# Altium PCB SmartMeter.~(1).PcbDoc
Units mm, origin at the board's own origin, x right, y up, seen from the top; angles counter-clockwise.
Board outline 36.42 x 43 mm, 2 copper layers (Top Layer, Bottom Layer), stack 0.071 mm thick; 33 components, 27 nets, 131 pads, 18 vias.
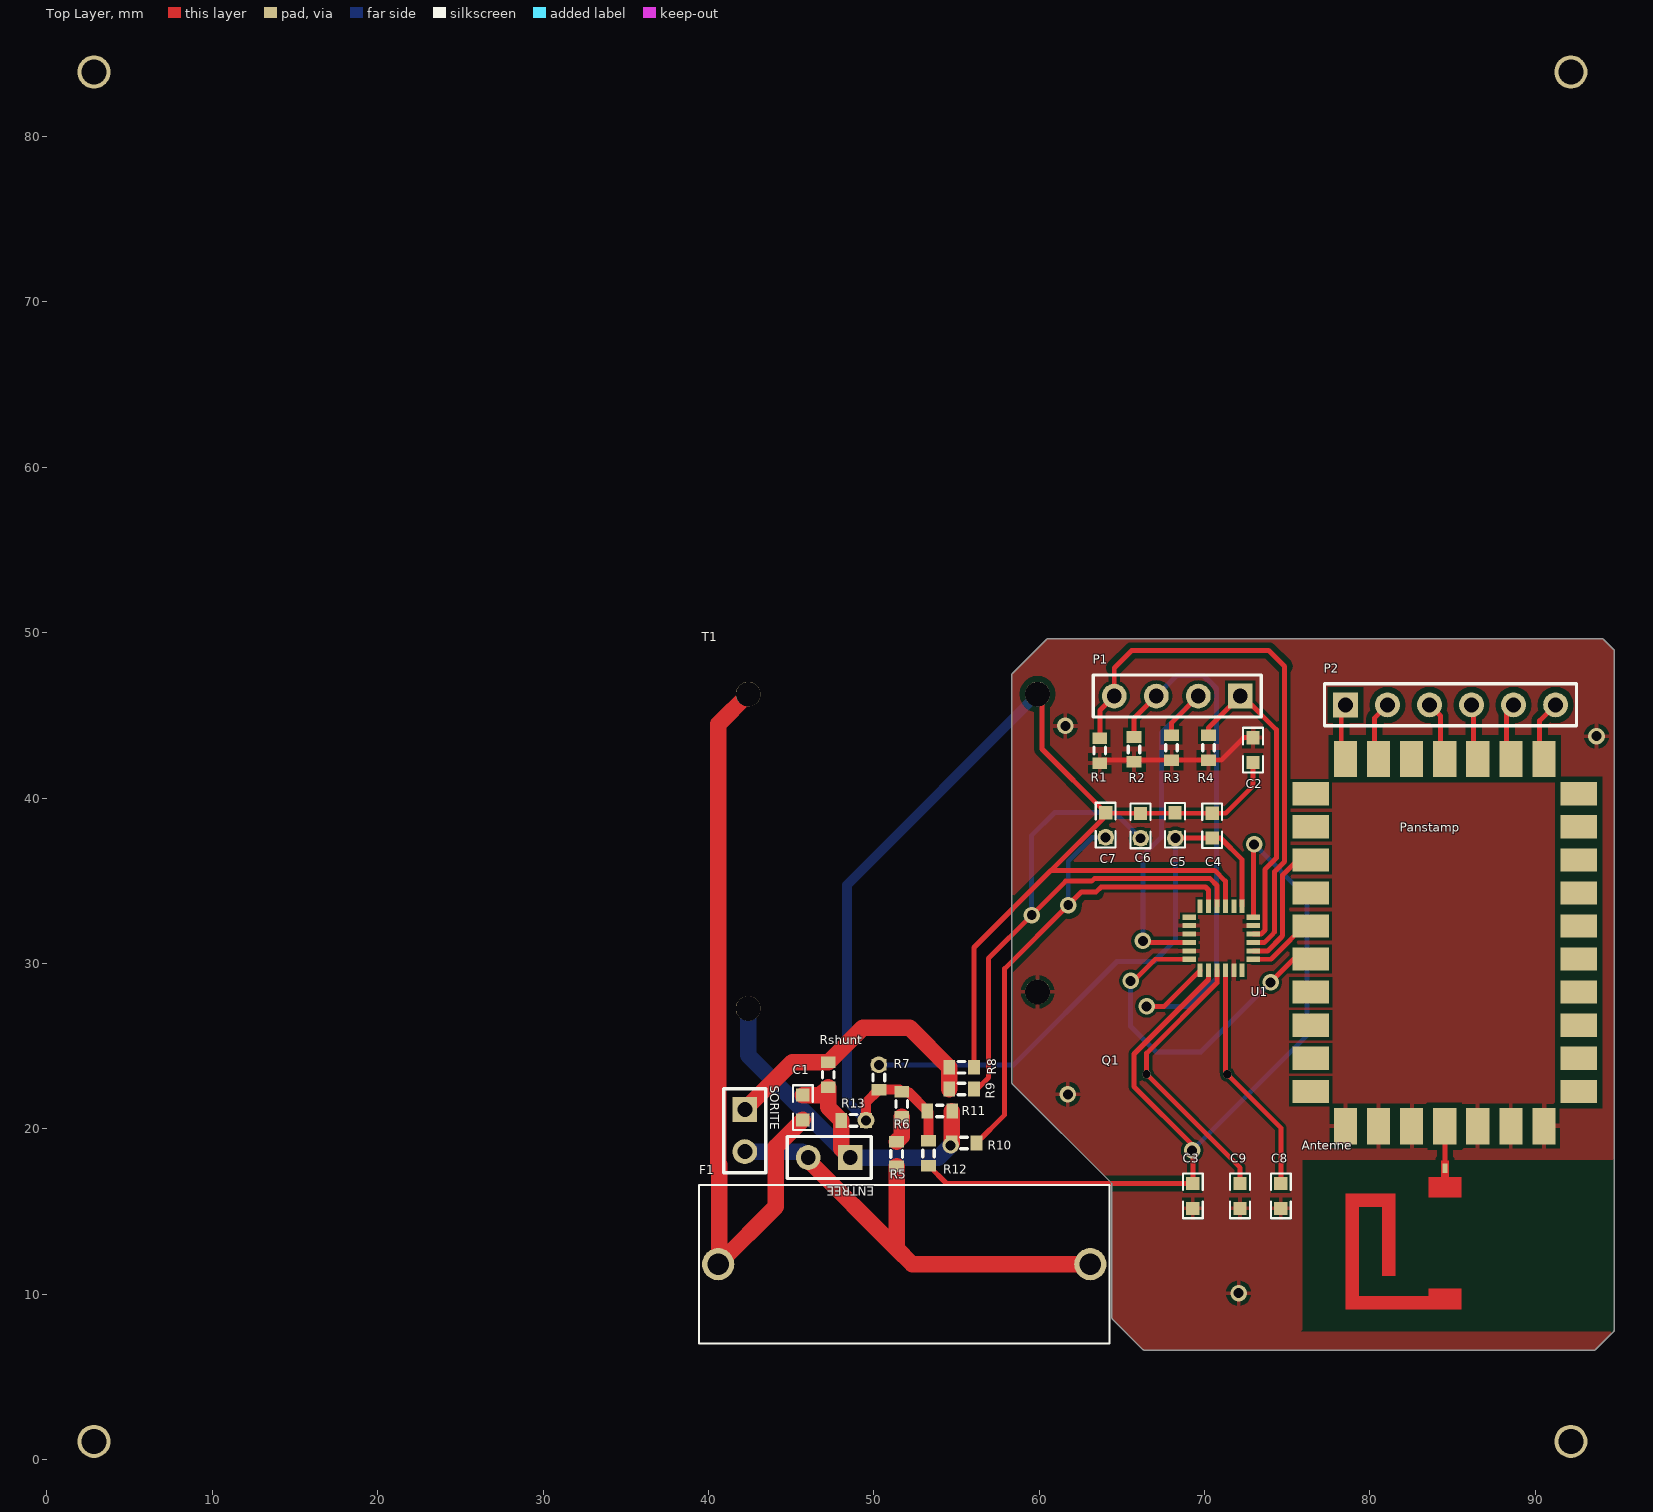
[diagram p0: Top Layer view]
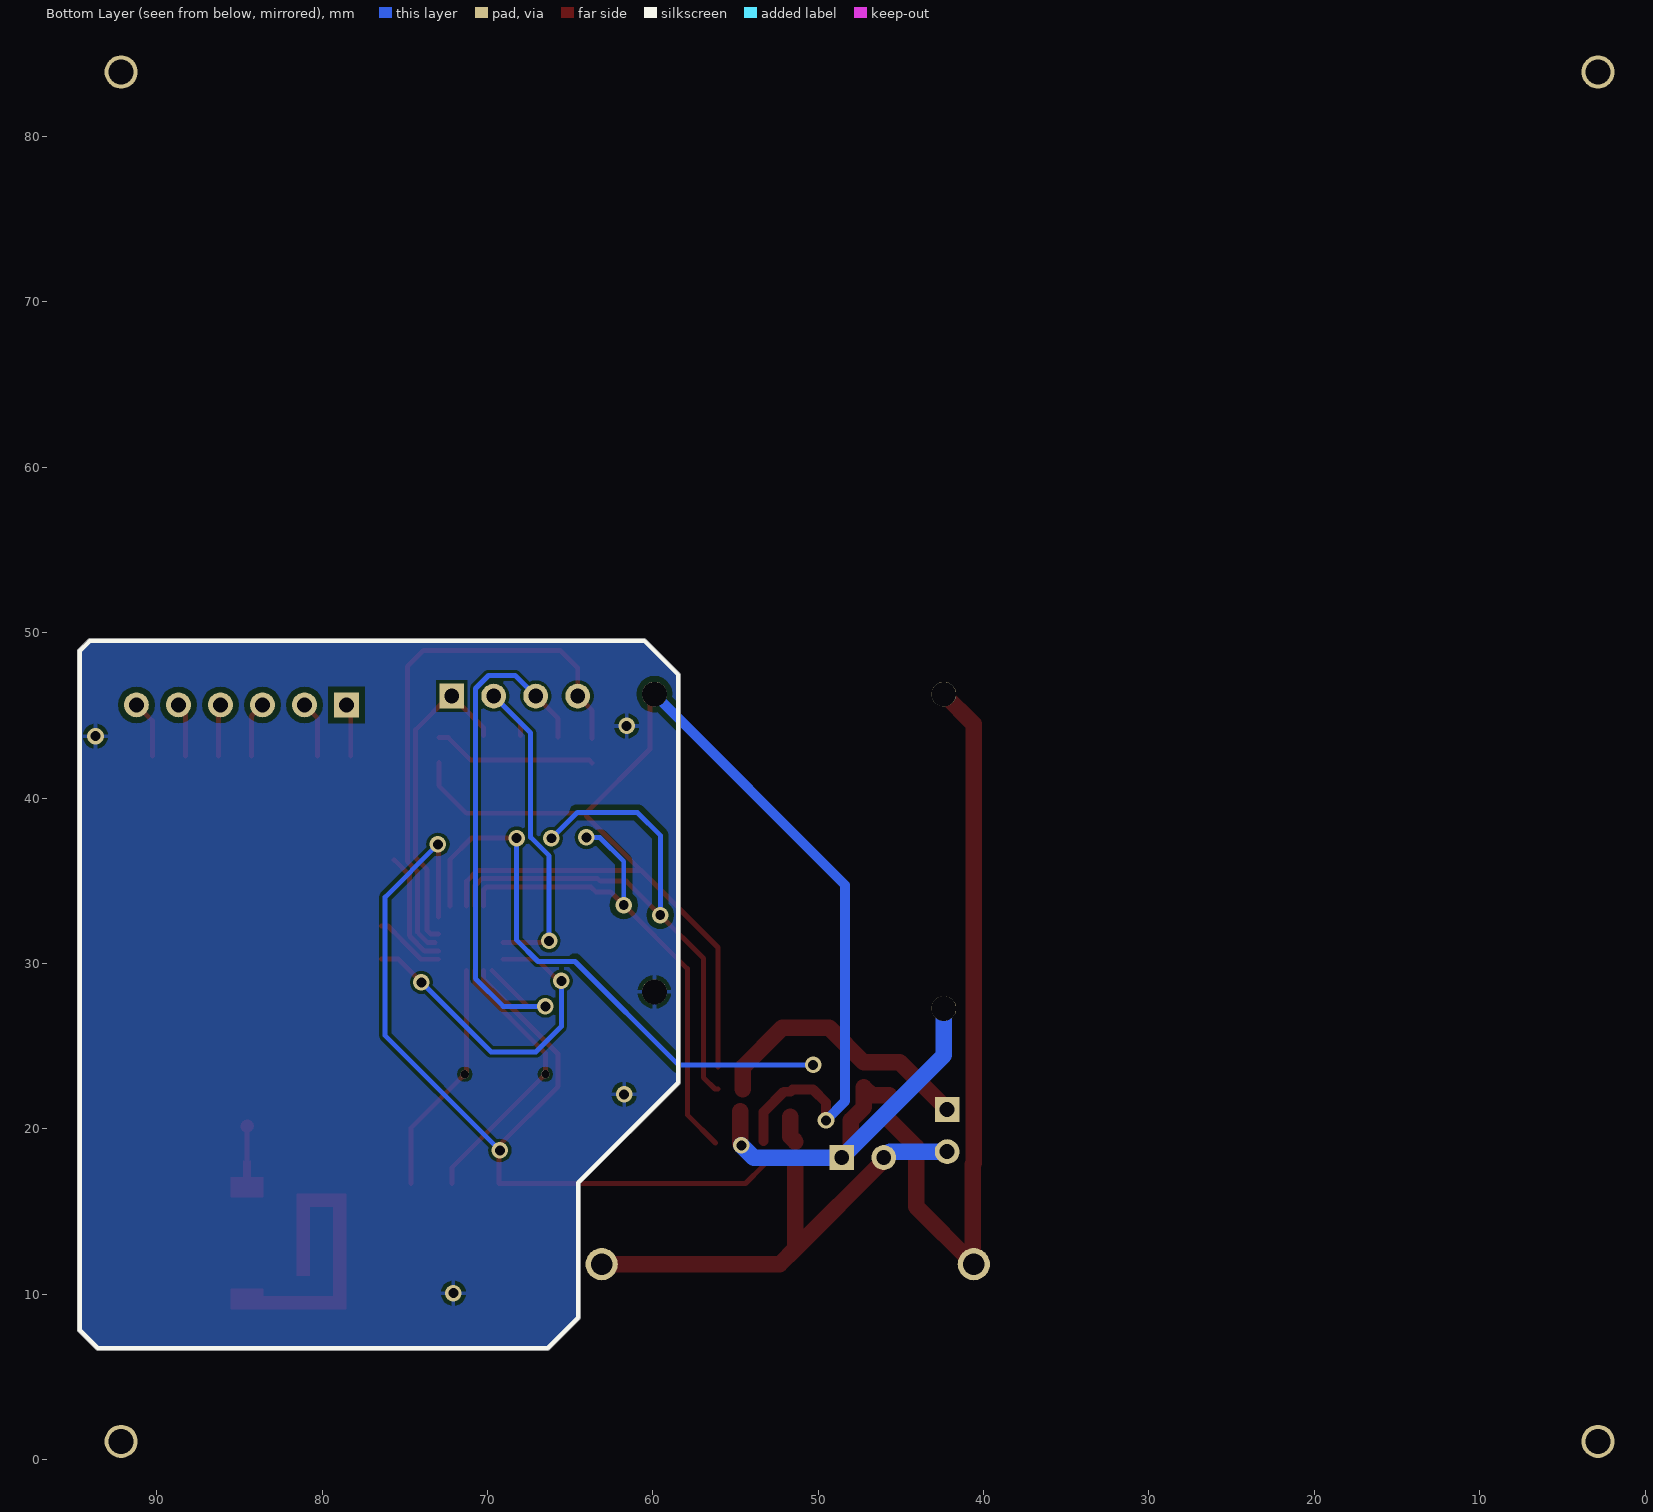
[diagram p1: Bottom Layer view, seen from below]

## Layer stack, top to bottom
Top Layer: signal copper 0.0356
Bottom Layer: signal copper 0.0356

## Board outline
58.393,22.694 64.401,16.686 64.401,8.572 ccw(c64.529,8.572) 64.439,8.482 66.267,6.654 ccw(c66.358,6.744) 66.358,6.616 93.561,6.616 ccw(c93.561,6.744) 93.651,6.654 94.743,7.746 94.743,7.745 ccw(c94.653,7.836) 94.78,7.836 94.78,48.882 ccw(c94.653,48.882) 94.743,48.973 94.743,48.972 94.134,49.582 ccw(c94.043,49.492) 94.043,49.619 60.515,49.619 ccw(c60.515,49.492) 60.425,49.582 58.393,47.55 58.394,47.55 ccw(c58.483,47.46) 58.356,47.46 58.356,22.784 ccw(c58.483,22.784)

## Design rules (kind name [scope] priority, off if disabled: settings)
Clearance Clearance_Max [InComponent('U1')] p1: gap=0.15
Clearance Clearance_INU [WithinRoom('INU')] p2: gap=0.2
Clearance [All] p3: gap=0.35
PolygonConnect [All] p1: connectstyle=Relief reliefconductorwidth=0.254 reliefentries=4 polygonreliefangle="90 Angle" airgapwidth=0.254
RoomDefinition INU [not IsComponent] p1: confinementstyle=ConfineIn formatcopy=TRUE lockcomponents=FALSE outline 63.055,13.373 76.772,13.373 76.772,48.476 63.055,48.476
RoutingVias [All] p1: holewidth=0.711 width=1.27 viastyle="Through Hole" minholewidth=0.711 minwidth=1.27 maxholewidth=0.711 maxwidth=1.27
SolderMaskExpansion [All] p1: expansion=0.102
UnpouredPolygon [All] p1: allowunpoured=FALSE
Width Width_INU [WithinRoom('INU')] p1: maxlimit=0.8 minlimit=0.2 preferedwidth=0.3 toplayer_maxwidth=0.4 minimp=50.000000 maximp=50.000000 favimp=50.000000
Width Width_HT [InNetClass('HT')] p2: maxlimit=3 minlimit=1 preferedwidth=2.184 minimp=50.000000 maximp=50.000000 favimp=50.000000
Width [All] p3: maxlimit=0.8 minlimit=0.3 preferedwidth=0.6 minimp=50.000000 maximp=50.000000 favimp=50.000000
29 further rules are at their usual default settings.

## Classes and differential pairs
net class HT: NetC1_1 NetC1_2 NetF1_1 NetR5_2 "NEUTRAL OUT"
component class "Components Class 1": U1
component class SmartMeter: C1 C2 C3 C4 C5 C6 C7 C8 C9 F1 P1 P2 Panstamp Q1 R1 R2 R3 R4 R5 R6 R7 R8 R9 R10 R11 R12 R13 Rshunt T1

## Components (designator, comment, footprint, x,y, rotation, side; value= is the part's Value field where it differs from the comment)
Antenne "Comment" PCBComponent_1#1 84.785,18.085 r180 top
C1 "100pF" "WCAP-CSGP 0603, H=0.8mm" 45.707,21.285 r90 top
C2 "100pF" "WCAP-CSGP 0603, H=0.8mm" 72.936,42.901 r90 top
C3 "100pF" "WCAP-CSGP 0603, H=0.8mm" 69.291,15.938 r270 top
C4 "1000pF" "WCAP-CSGP 0603, H=0.8mm" 70.46,38.329 r270 top
C5 "100pF" "WCAP-CSGP 0603, H=0.8mm" 68.212,38.354 r270 top
C6 "1uF" "WCAP-CSGP 0603, H=0.8mm" 66.129,38.316 r90 top
C7 "1uF" "WCAP-CSGP 0603, H=0.8mm" 64.021,38.367 r270 top
C8 "18pF" "WCAP-CSGP 0603, H=0.8mm" 74.612,15.938 r270 top
C9 "18pF" "WCAP-CSGP 0603, H=0.8mm" 72.149,15.938 r270 top
ENTREE "Comment" HDR1X2 48.578,18.263 r180 top
F1 "696103201002" 696103201002 51.841,11.811 r180 top
P1 "Header 4" HDR1X4 72.161,46.164 r180 top
P2 "Header 6" HDR1X6 78.524,45.631 r0 top
Panstamp "Panstamp" PCBComponent_1#2 92.621,22.263 r180 top
Q1 "Comment" PCBComponent_1#3 71.374,23.292 r180 top
R1 "Res3" J1-0603 63.665,42.862 r270 top
R2 "Res3" J1-0603 65.735,42.939 r270 top
R3 "Res3" J1-0603 68.008,43.04 r270 top
R4 "Res3" J1-0603 70.244,43.04 r270 top
R5 "Res3" J1-0603 51.384,18.479 r90 top
R6 "Res3" J1-0603 51.689,21.488 r90 top
R7 "Res3" J1-0603 50.305,23.114 r270 top
R8 "Res3" J1-0603 55.308,23.724 r0 top
R9 "Res3" J1-0603 55.308,22.403 r180 top
R10 "Res3" J1-0603 55.461,19.139 r180 top
R11 "Res3" J1-0603 53.988,21.082 r0 top
R12 "Res3" J1-0603 53.315,18.517 r90 top
R13 "Res3" J1-0603 48.781,20.511 r180 top
Rshunt "Res3" J1-0603 47.244,23.266 r90 top
SORITE "Comment" HDR1X2 42.202,21.158 r270 top
T1 "Alimentation 230AC/3.3DC" PCBComponent_1#4 42.405,46.279 r0 top
U1 "Maxim_78M6610+LMU" 21_0139I_T2444_4 71.006,31.521 r0 top

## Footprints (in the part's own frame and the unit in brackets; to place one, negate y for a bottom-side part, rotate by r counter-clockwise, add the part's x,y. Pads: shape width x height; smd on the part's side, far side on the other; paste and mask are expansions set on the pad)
21_0139I_T2444_4 [mil]
  rect 32x12 smd: 1(-76.5,50) 2(-76.5,30) 3(-76.5,10) 4(-76.5,-10) 5(-76.5,-30) 6(-76.5,-50) 13(76.5,-50) 14(76.5,-30) 15(76.5,-10) 16(76.5,10) 17(76.5,30) 18(76.5,50)
  rect 12x32 smd: 7(-50,-76.5) 8(-30,-76.5) 9(-10,-76.5) 10(10,-76.5) 11(30,-76.5) 12(50,-76.5) 19(50,76.5) 20(30,76.5) 21(10,76.5) 22(-10,76.5) 23(-30,76.5) 24(-50,76.5)
696103201002 [mm] "PCB - Clip Cover - THR"
  round 1.95 hole 1.3: 1(-11.25,0) 2(11.25,0)
  silkscreen extent -12.4,-4.8 12.4,4.8, body extent -12.4,-4.8 12.4,4.8, height 25
HDR1X2 [mm] "Connector; Header; 2 Position"
  rect 1.5x1.5 hole 0.9: 1(0,0)
  round 1.5 hole 0.9: 2(2.54,0)
  silkscreen extent -1.27,-1.27 3.81,1.27
HDR1X4 [mm] "Connector; Header; 4 Position"
  rect 1.5x1.5 hole 0.9: 1(0,0)
  round 1.5 hole 0.9: 2(2.54,0) 3(5.08,0) 4(7.62,0)
  silkscreen extent -1.27,-1.27 8.89,1.27
HDR1X6 [mm] "Connector; Header; 6 Position"
  rect 1.5x1.5 hole 0.9: 1(0,0)
  round 1.5 hole 0.9: 2(2.54,0) 3(5.08,0) 4(7.62,0) 5(10.16,0) 6(12.7,0)
  silkscreen extent -1.27,-1.27 13.97,1.27
J1-0603 [mm] "Chip Resistor, Body 1.6x0.8mm, IPC High Density"
  rect 0.7x0.9 smd: 1(-0.75,0) 2(0.75,0)
  silkscreen extent -0.2,-0.35 0.2,0.35, body extent -0.85,-0.48 0.85,0.48, height 0.9
PCBComponent_1#1 [mm]
  rect 0.3x0.6 smd: 0(0.245,0.47)
  Top Layer region: 0,0 0.5,0 0.5,1 0,1
  Top Layer region: -0.75,1 1.25,1 1.25,2.25 -0.75,2.25
  Top Layer region: -0.75,7.75 1.25,7.75 1.25,9 -0.75,9
  Top Layer region: 1.25,8.2 6.25,8.2 6.25,9 1.25,9
  Top Layer region: 5.45,2 6.25,2 6.25,9 5.45,9
  Top Layer region: 3.25,2 5.45,2 5.45,2.8 3.25,2.8
  Top Layer region: 3.25,2 4.05,2 4.05,7 3.25,7
PCBComponent_1#2 [mm]
  rect 2.2x1.4 smd: 1(0,0) 2(0,-1.999) 3(0,-4) 4(0,-6) 5(0,-8) 6(0,-10) 7(0,-12) 8(0,-14) 9(0,-16) 10(0,-18) 18(16.2,-18) 19(16.2,-16) 20(16.2,-14) 21(16.2,-12) 22(16.2,-10) 23(16.2,-8) 24(16.2,-6) 25(16.2,-4) 26(16.2,-2) 27(16.2,0)
  rect 1.4x2.2 smd: 11(2.1,-20.1) 12(4.1,-20.1) 13(6.1,-20.1) 14(8.1,-20.1) 15(10.1,-20.1) 16(12.1,-20.1) 17(14.1,-20.1) 28(14.1,2.1) 29(12.1,2.1) 30(10.1,2.1) 31(8.1,2.1) 32(6.1,2.1) 33(4.1,2.1) 34(2.1,2.1)
PCBComponent_1#3 [mm]
  round 0.5 hole 0.5: 1(0,0) 2(4.877,0)
PCBComponent_1#4 [mm]
  round 1.5 hole 1.5: 1(17.5,-18) 2(17.5,0) 3(0,0) 4(0,-19)
"WCAP-CSGP 0603, H=0.8mm" [mm] "MLCC 0603, H=0.8mm"
  rect 0.8x0.8 smd: 1(-0.75,0) 2(0.75,0)
  silkscreen extent -1.35,-0.6 1.35,0.6, body extent -0.8,-0.4 0.8,0.4, height 0.77

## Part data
C1 C2 C3 C4 C5 C6 C7 C8 C9: library part 0603C-1UF-10V-X5R-TDK, "CAPACITOR 0603 CERAMIC"
ENTREE SORITE: library part "Header 2"
F1: library part "WR-FSH, 696103201002", "WR-FSH Fuseholder THR Blocks PCB Clip Cover"
P1: "Header, 4-Pin"
P2: "Header, 6-Pin"
Panstamp: "Panstamp NRG 2.0"
Q1: library part Component_1
R1 R2 R3 R4 R5 R6 R7 R8 R9 R10 R11 R12 R13 Rshunt: "Resistor"
U1: library part "Maxim78M6610 + LMU", "Mesure d'énergie IC ENERGY MM PROCESSOR 24TQFN"

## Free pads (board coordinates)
  round 2 hole 1.5: 1(2.85,83.9) 2(92.15,83.9) 3(92.15,1.1) 4(2.85,1.1)

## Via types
v1: diameter 1, hole 0.6, Top Layer to Bottom Layer, 18 vias

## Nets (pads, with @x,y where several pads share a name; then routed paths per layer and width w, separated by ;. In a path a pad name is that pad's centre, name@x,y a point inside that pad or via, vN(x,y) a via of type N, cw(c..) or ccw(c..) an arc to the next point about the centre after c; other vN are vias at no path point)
Antenne: Antenne.0 Panstamp.31 | length 2.6
  Top Layer w0.3: Antenne.0 Panstamp.31@84.54,20.144
  Top Layer w0.8: Panstamp.31 Panstamp.31@84.54,20.144
GND: C2.2 C3.2 C8.2 C9.2 Panstamp.28 Panstamp.29 Panstamp.30 Panstamp.32 Panstamp.33 Panstamp.34 R1.2 R2.2 R3.2 R4.2 T1.1 U1.2 U1.3 U1.5 U1.11 U1.17 | length 9.9
  Top Layer w0.3: R1.2 63.843,42.29 R3.2 R4.2 71.005,42.29 72.365,43.651 C2.2
  other v1: 72.06,10.058 61.735,22.085 93.701,43.739 61.582,44.361
NetC1_1: C1.1 F1.2 T1.3 | length 46
  Top Layer w1: F1.2 F1.2@40.653,11.872 ; T1.3 40.602,44.476 40.602,17.905 40.653,17.854 F1.2@40.653,11.872 ; C1.1 44.082,18.91 44.082,15.301 F1.2@40.653,11.872
NetC1_2: C1.2 ENTREE.1 R10.2 R11.2 R13.2 Rshunt.1 T1.4 | length 26.4
  Top Layer w1: C1.2 46.763,22.035 Rshunt.1 47.244,21.297 R13.2 48.031,18.809 ENTREE.1 ; R10.2 R11.2@54.711,21.061
  Bottom Layer w1: T1.4 42.405,24.435 ENTREE.1 53.911,18.263 v1(54.648,18.999)
NetC2_1: C2.1 C4.1 C5.1 C6.2 C7.1 R6.2 R7.2 R8.2 R11.1 R12.2 R13.1 T1.2 U1.21 | length 89.4
  Top Layer w0.3: R8.2 56.059,30.963 60.719,35.623 ; T1.2 60.172,46.012 60.172,42.965 C7.1 ; U1.21 71.26,34.976 70.612,35.623 60.719,35.623 ; C2.1 72.936,40.742 71.273,39.079 C4.1 64.059,39.079 C7.1 ; 60.719,35.623 60.733,35.623 64.021,38.912 C7.1
  Top Layer w0.6: v1(49.531,20.511) 49.531,21.59 R7.2 51.563,22.364 R6.2 52.081,22.238 R11.1 53.315,21.005 R12.2
  Bottom Layer w0.6: v1(49.531,20.511) 48.374,21.667 48.374,34.748 T1.2
NetC3_1: C3.1 R12.1 U1.8 U1.18 | length 59.8
  Top Layer w0.3: R12.1 54.393,16.688 C3.1 69.291,18.999 65.739,22.551 65.739,24.524 70.244,29.028 U1.8 ; U1.18 72.949,37.148 v1(73,37.198)
  Bottom Layer w0.3: v1(69.253,18.694) 76.187,25.629 76.187,34.011 v1(73,37.198)
NetC4_2: C4.2 C5.2 R7.1 U1.19 | length 34.6
  Top Layer w0.3: v1(68.237,37.579) C4.2 70.968,37.579 72.276,36.27 U1.19
  Bottom Layer w0.3: v1(50.305,23.864) 58.459,23.864 64.706,30.112 66.942,30.112 68.237,31.407 v1(68.237,37.579)
NetC6_1: C6.1 R9.1 U1.22 | length 38.2
  Top Layer w0.3: R9.1 56.245,22.403 56.934,23.092 56.934,30.302 v1(59.55,32.918) 61.605,34.974 63.18,34.974 63.33,35.124 70.337,35.124 70.752,34.709 U1.22
  Bottom Layer w0.3: v1(59.55,32.918) 59.55,37.744 60.934,39.128 64.567,39.128 v1(66.129,37.566)
NetC7_2: C7.2 R10.1 U1.23 | length 32.2
  Top Layer w0.3: R10.1 57.912,20.84 57.912,29.68 v1(61.76,33.528) 62.556,34.324 63.449,34.324 63.749,34.624 70.063,34.624 70.244,34.442 U1.23
  Bottom Layer w0.3: v1(61.76,33.528) 61.76,36.17 63.207,37.617 v1(64.021,37.617)
NetC8_1: C8.1 Q1.1 U1.10 | length 14.3
  Top Layer w0.3: U1.10 71.26,23.406 Q1.1 74.612,20.053 C8.1
NetC9_1: C9.1 Q1.2 U1.9 | length 17
  Top Layer w0.3: U1.9 70.752,28.829 66.497,24.575 Q1.2 72.149,17.64 C9.1
NetF1_1: ENTREE.2 F1.1 R5.1 SORITE.2 | length 28.8
  Top Layer w1: ENTREE.2 46.038,18.101 51.384,12.754 ; R5.1 51.384,12.754 ; F1.1 52.327,11.811 51.384,12.754
  Bottom Layer w1: SORITE.2 45.682,18.618 ENTREE.2
NetP1_1: P1.1 R4.1 U1.16 | length 19.4
  Top Layer w0.3: R4.1 70.244,44.247 P1.1 72.309,46.164 74.341,44.133 74.341,36.373 73.655,35.687 73.655,32.007 73.424,31.775 U1.16
NetP1_2: P1.2 R3.1 U1.4 | length 22.1
  Top Layer w0.3: v1(66.269,31.356) 66.358,31.267 U1.4 ; R3.1 68.008,44.552 P1.2
  Bottom Layer w0.3: v1(66.269,31.356) 66.269,36.504 67.387,37.622 67.387,43.93 P1.2
NetP1_3: P1.3 R2.1 U1.7 | length 34.1
  Top Layer w0.3: R2.1 65.735,44.818 P1.3 ; v1(66.497,27.407) 67.564,27.407 U1.7
  Bottom Layer w0.3: v1(66.497,27.407) 69.05,27.407 70.721,29.078 70.721,46.62 69.932,47.409 68.326,47.409 P1.3
NetP1_4: P1.4 R1.1 U1.15 | length 33.4
  Top Layer w0.3: R1.1 63.665,45.288 P1.4 64.541,47.866 65.596,48.92 73.876,48.92 74.841,47.955 74.841,36.166 74.227,35.551 74.227,31.89 74.155,31.818 74.155,31.8 73.607,31.251 73.164,31.251 U1.15@73.156,31.259
NetP2_1: P2.1 Panstamp.17 | length 2.8
  Top Layer w0.3: Panstamp.17@78.267,42.528 P2.1@78.267,45.374
NetP2_2: P2.2 Panstamp.16 | length 3.4
  Top Layer w0.3: Panstamp.16@80.267,42.528 80.267,44.834 P2.2
NetP2_3: P2.3 Panstamp.14 | length 3.4
  Top Layer w0.3: P2.3 84.267,44.968 Panstamp.14@84.267,42.528
NetP2_4: P2.4 Panstamp.13 | length 3.2
  Top Layer w0.3: P2.4 86.267,45.508 Panstamp.13@86.267,42.528
NetP2_5: P2.5 Panstamp.12 | length 3.3
  Top Layer w0.3: Panstamp.12@88.267,42.528 88.267,45.214 P2.5
NetP2_6: P2.6 Panstamp.11 | length 3.5
  Top Layer w0.3: Panstamp.11@90.267,42.528 90.267,44.674 P2.6
NetPanstamp_20: Panstamp.20 U1.14 | length 7.1
  Top Layer w0.3: U1.14 72.957,30.751 73.814,30.751 74.655,31.593 74.655,31.611 74.727,31.682 74.727,35.344 Panstamp.20@75.646,36.263
NetPanstamp_22: Panstamp.22 U1.13 | length 4.3
  Top Layer w0.3: U1.13 74.021,30.251 75.155,31.385 75.155,31.404 76.015,32.263 Panstamp.22
NetPanstamp_23: Panstamp.23 U1.6 | length 20.7
  Top Layer w0.3: v1(65.532,28.943) 65.71,28.943 67.018,30.251 U1.6 ; v1(73.99,28.854) 75.399,30.263 Panstamp.23
  Bottom Layer w0.3: v1(65.532,28.943) 65.532,26.187 67.069,24.651 69.787,24.651 v1(73.99,28.854)
NetR5_2: R5.2 R6.1 | length 1.6
  Top Layer w1: R5.2 51.689,19.533 R6.1
"NEUTRAL OUT": R8.1 R9.2 Rshunt.2 SORITE.1 | length 16.7
  Top Layer w1: SORITE.1 45.06,24.016 Rshunt.2 49.326,26.098 52.184,26.098 R8.1 R9.2
pads on no net: Panstamp.1 Panstamp.2 Panstamp.3 Panstamp.4 Panstamp.5 Panstamp.6 Panstamp.7 Panstamp.8 Panstamp.9 Panstamp.10 Panstamp.15 Panstamp.18 Panstamp.19 Panstamp.21 Panstamp.24 Panstamp.25 Panstamp.26 Panstamp.27 U1.1 U1.12 U1.20 U1.24

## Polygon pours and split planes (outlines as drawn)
GND on Top Layer "GND-plane" (solid, pour order 7): 58.386,47.557 60.458,49.63 60.515,49.63 94.067,49.63 94.092,49.604 94.791,48.906 94.791,48.882 94.791,18.214 94.856,18.148 94.831,18.123 75.895,18.123 75.895,7.836 75.806,7.747 75.815,7.738 94.751,7.738 94.736,7.738 93.651,6.654 93.629,6.631 66.309,6.631 66.309,6.655 64.391,8.572 64.401,8.583 64.401,16.686 64.401,16.728 58.346,22.784
GND on Bottom Layer "GND-plane" (solid, pour order 9): 58.386,47.557 60.411,49.582 60.425,49.582 94.07,49.582 94.092,49.604 94.791,48.906 94.791,48.882 94.791,7.813 94.766,7.787 93.584,6.606 93.561,6.606 66.334,6.606 66.309,6.631 64.415,8.525 64.415,8.527 64.415,16.672 64.401,16.686 58.346,22.742 58.346,22.784

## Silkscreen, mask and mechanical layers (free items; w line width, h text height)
Bottom Overlay:
  lines w0.254: 93.548,6.744 93.561,6.744 ; 93.561,6.744 66.358,6.744 64.529,8.572 64.529,16.739 58.483,22.784 58.483,47.46 60.515,49.492 94.043,49.492 94.653,48.882 94.653,7.836 93.561,6.744
Mechanical 1:
  lines w0.254: 0,-0.749 95,-0.749 95,85.979 0,85.979 0,-0.749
